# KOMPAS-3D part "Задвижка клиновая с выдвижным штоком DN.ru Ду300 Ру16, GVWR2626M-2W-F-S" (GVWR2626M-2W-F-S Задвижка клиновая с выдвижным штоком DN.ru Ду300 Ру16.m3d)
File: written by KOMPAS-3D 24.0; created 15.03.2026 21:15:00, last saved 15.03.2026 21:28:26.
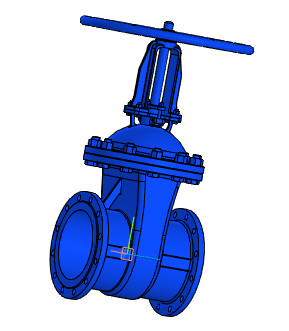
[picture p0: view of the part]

Document properties: Автор: R2D2; Полное имя файла: E:\Работа\Зайцев\GVWR2626M-2W-F-S Задвижка клиновая с выдвижным штоком DN.ru Ду50-300 Ру16\DN300\GVWR2626M-2W-F-S Задвижка клиновая с выдвижным штоком DN.ru Ду300 Ру16.m3d

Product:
- Part/product: Задвижка клиновая с выдвижным штоком DN.ru Ду300 Ру16  | designation GVWR2626M-2W-F-S
    Масса: 215
    Раздел спецификации: Прочие изделия
    Примечание: D040-10507

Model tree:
1. Операция без истории:1

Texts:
  GVWR2626M-2W-F-S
